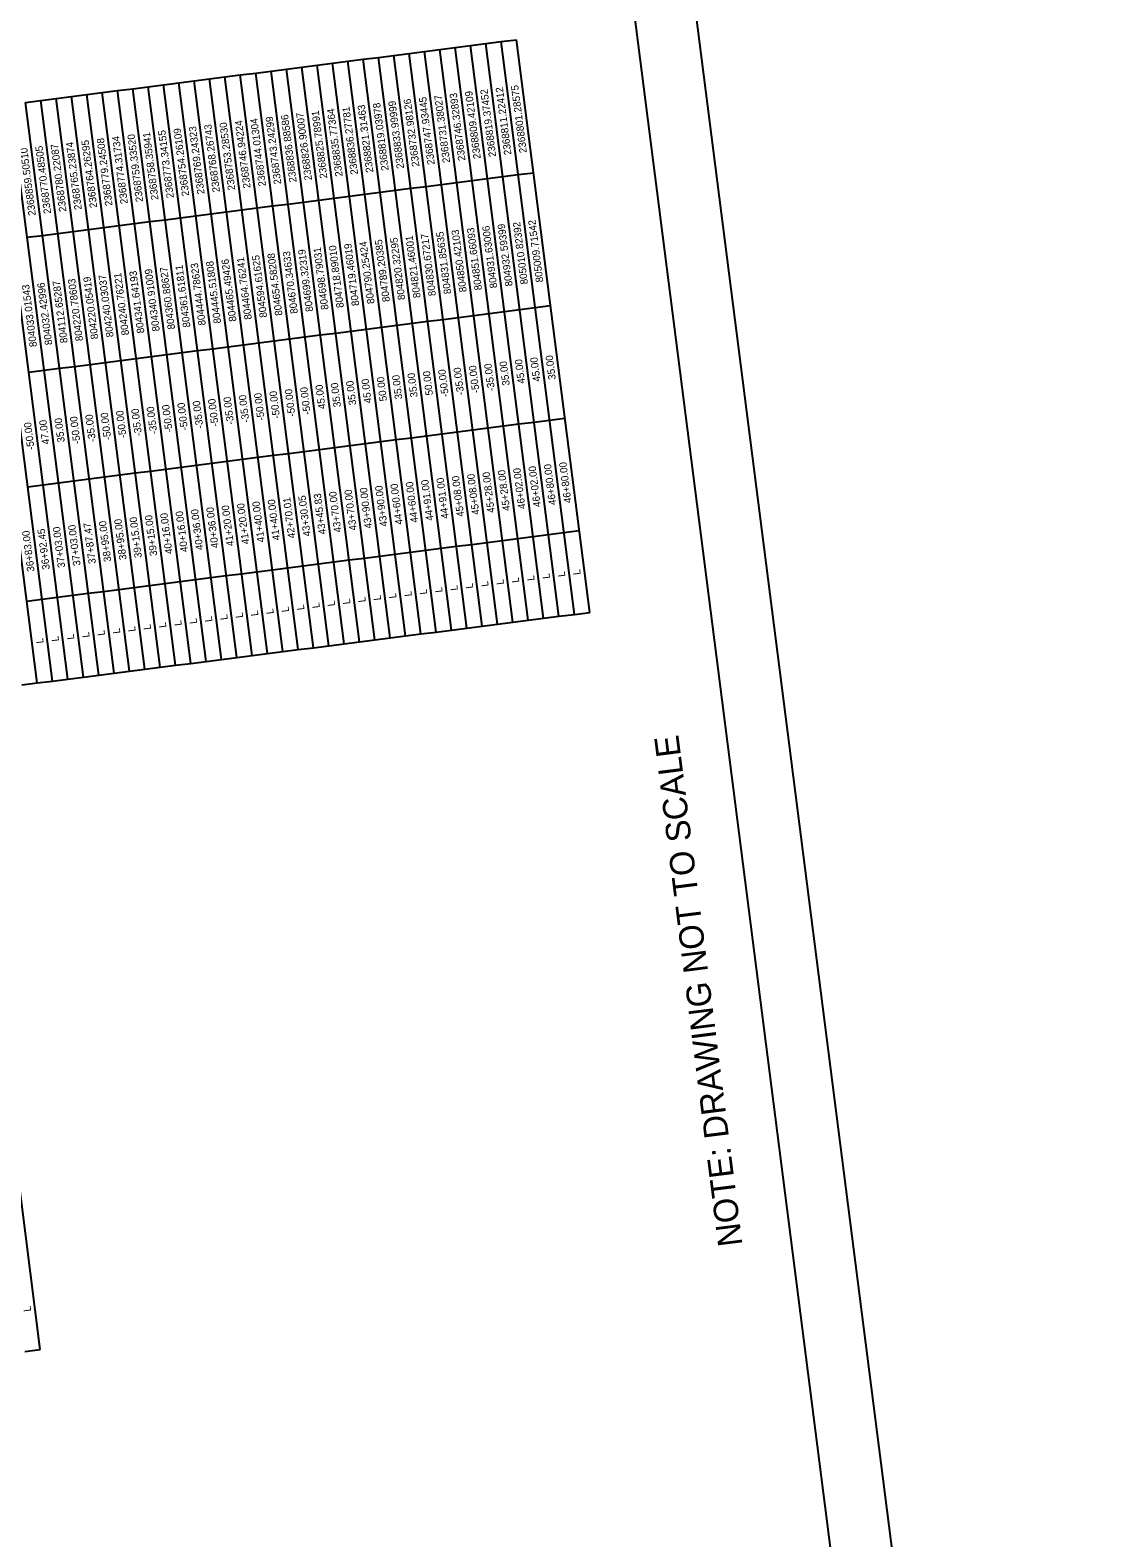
# Model space of a CAD drawing. Extents: x 2364621 to 2374814, y 792603 to 806745.
# Drawn here: x 2371409 to 2374814, y 798784 to 803612 of the extents above; entities that cross this region are included whole.
import ezdxf

# ---------------------------------------------------------------- set-up
doc = ezdxf.new("R2010")
doc.units = 0
for name, color, linetype in [('CTL Sheet Border CELL', 7, 'Continuous'), ('CTL Sheet Table Cell', 7, 'Continuous'), ('CTL Sheet Text', 7, 'Continuous'), ('Scratch_Level_0', 7, 'Continuous')]:
    doc.layers.add(name, color=color, linetype=linetype)

msp = doc.modelspace()

# ---------------------------------------------------------------- linework, layer by layer
at = {"layer": 'CTL Sheet Border CELL'}
msp.add_lwpolyline([(2364831.4, 805549.1), (2366316.3, 793922.1), (2374455.2, 794961.6), (2372970.2, 806588.6)], close=True, dxfattribs=at)
at = {"layer": 'CTL Sheet Table Cell'}
for p, q in [((2372917.1, 803575), (2372966.3, 803581.2)), ((2373200.5, 801747.5), (2372966.3, 803581.2)), ((2372524.2, 803524.8), (2372573.3, 803531)), ((2372573.3, 803531), (2372622.4, 803537.3)), ((2372807.5, 801697.3), (2372573.3, 803531)), ((2372622.4, 803537.3), (2372671.6, 803543.6)), ((2372856.6, 801703.6), (2372622.4, 803537.3)), ((2372671.6, 803543.6), (2372720.7, 803549.9)), ((2372905.8, 801709.9), (2372671.6, 803543.6)), ((2372720.7, 803549.9), (2372769.8, 803556.1)), ((2372954.9, 801716.1), (2372720.7, 803549.9)), ((2372769.8, 803556.1), (2372818.9, 803562.4)), ((2373004, 801722.4), (2372769.8, 803556.1)), ((2372818.9, 803562.4), (2372868, 803568.7)), ((2373053.1, 801728.7), (2372818.9, 803562.4)), ((2372868, 803568.7), (2372917.1, 803575)), ((2373102.2, 801735), (2372868, 803568.7)), ((2373151.4, 801741.2), (2372917.1, 803575)), ((2372180.4, 803480.9), (2372229.5, 803487.1)), ((2372229.5, 803487.1), (2372278.6, 803493.4)), ((2372463.7, 801653.4), (2372229.5, 803487.1)), ((2372278.6, 803493.4), (2372327.7, 803499.7)), ((2372512.8, 801659.7), (2372278.6, 803493.4)), ((2372327.7, 803499.7), (2372376.9, 803506)), ((2372561.9, 801665.9), (2372327.7, 803499.7)), ((2372376.9, 803506), (2372426, 803512.2)), ((2372611.1, 801672.2), (2372376.9, 803506)), ((2372426, 803512.2), (2372475.1, 803518.5)), ((2372660.2, 801678.5), (2372426, 803512.2)), ((2372475.1, 803518.5), (2372524.2, 803524.8)), ((2372709.3, 801684.8), (2372475.1, 803518.5)), ((2372758.4, 801691), (2372524.2, 803524.8)), ((2371787.4, 803430.7), (2371836.6, 803436.9)), ((2371836.6, 803436.9), (2371885.7, 803443.2)), ((2372070.8, 801603.2), (2371836.6, 803436.9)), ((2371885.7, 803443.2), (2371934.8, 803449.5)), ((2372119.9, 801609.5), (2371885.7, 803443.2)), ((2371934.8, 803449.5), (2371983.9, 803455.8)), ((2372169, 801615.8), (2371934.8, 803449.5)), ((2371983.9, 803455.8), (2372033, 803462)), ((2372218.1, 801622), (2371983.9, 803455.8)), ((2372033, 803462), (2372082.1, 803468.3)), ((2372267.2, 801628.3), (2372033, 803462)), ((2372082.1, 803468.3), (2372131.3, 803474.6)), ((2372316.3, 801634.6), (2372082.1, 803468.3)), ((2372131.3, 803474.6), (2372180.4, 803480.9)), ((2372365.5, 801640.9), (2372131.3, 803474.6)), ((2372414.6, 801647.1), (2372180.4, 803480.9)), ((2371394.5, 803380.5), (2371443.6, 803386.8)), ((2371443.6, 803386.8), (2371492.7, 803393)), ((2371677.8, 801553), (2371443.6, 803386.8)), ((2371492.7, 803393), (2371541.8, 803399.3)), ((2371726.9, 801559.3), (2371492.7, 803393)), ((2371541.8, 803399.3), (2371591, 803405.6)), ((2371776, 801565.6), (2371541.8, 803399.3)), ((2371591, 803405.6), (2371640.1, 803411.9)), ((2371825.2, 801571.8), (2371591, 803405.6)), ((2371640.1, 803411.9), (2371689.2, 803418.1)), ((2371874.3, 801578.1), (2371640.1, 803411.9)), ((2371689.2, 803418.1), (2371738.3, 803424.4)), ((2371923.4, 801584.4), (2371689.2, 803418.1)), ((2371738.3, 803424.4), (2371787.4, 803430.7)), ((2371972.5, 801590.7), (2371738.3, 803424.4)), ((2372021.6, 801596.9), (2371787.4, 803430.7)), ((2371432.2, 801521.7), (2371198, 803355.4)), ((2371481.3, 801527.9), (2371247.1, 803361.7)), ((2371530.5, 801534.2), (2371296.3, 803367.9)), ((2371579.6, 801540.5), (2371345.4, 803374.2)), ((2371628.7, 801546.8), (2371394.5, 803380.5)), ((2372922.4, 803143), (2372971.5, 803149.3)), ((2372971.5, 803149.3), (2373020.6, 803155.5)), ((2372529.5, 803092.8), (2372578.6, 803099.1)), ((2372578.6, 803099.1), (2372627.7, 803105.4)), ((2372627.7, 803105.4), (2372676.8, 803111.6)), ((2372676.8, 803111.6), (2372725.9, 803117.9)), ((2372725.9, 803117.9), (2372775, 803124.2)), ((2372775, 803124.2), (2372824.2, 803130.5)), ((2372824.2, 803130.5), (2372873.3, 803136.7)), ((2372873.3, 803136.7), (2372922.4, 803143)), ((2372136.5, 803042.6), (2372185.6, 803048.9)), ((2372185.6, 803048.9), (2372234.7, 803055.2)), ((2372234.7, 803055.2), (2372283.9, 803061.4)), ((2372283.9, 803061.4), (2372333, 803067.7)), ((2372333, 803067.7), (2372382.1, 803074)), ((2372382.1, 803074), (2372431.2, 803080.3)), ((2372431.2, 803080.3), (2372480.3, 803086.5)), ((2372480.3, 803086.5), (2372529.5, 803092.8)), ((2371743.6, 802992.4), (2371792.7, 802998.7)), ((2371792.7, 802998.7), (2371841.8, 803005)), ((2371841.8, 803005), (2371890.9, 803011.3)), ((2371890.9, 803011.3), (2371940, 803017.5)), ((2371940, 803017.5), (2371989.2, 803023.8)), ((2371989.2, 803023.8), (2372038.3, 803030.1)), ((2372038.3, 803030.1), (2372087.4, 803036.4)), ((2372087.4, 803036.4), (2372136.5, 803042.6)), ((2371399.7, 802948.5), (2371448.9, 802954.8)), ((2371448.9, 802954.8), (2371498, 802961.1)), ((2371498, 802961.1), (2371547.1, 802967.3)), ((2371547.1, 802967.3), (2371596.2, 802973.6)), ((2371596.2, 802973.6), (2371645.3, 802979.9)), ((2371645.3, 802979.9), (2371694.5, 802986.2)), ((2371694.5, 802986.2), (2371743.6, 802992.4)), ((2372878.5, 802704.8), (2372927.6, 802711)), ((2372927.6, 802711), (2372976.8, 802717.3)), ((2372976.8, 802717.3), (2373025.9, 802723.6)), ((2373025.9, 802723.6), (2373075, 802729.9)), ((2372485.6, 802654.6), (2372534.7, 802660.9)), ((2372534.7, 802660.9), (2372583.8, 802667.1)), ((2372583.8, 802667.1), (2372632.9, 802673.4)), ((2372632.9, 802673.4), (2372682.1, 802679.7)), ((2372682.1, 802679.7), (2372731.2, 802685.9)), ((2372731.2, 802685.9), (2372780.3, 802692.2)), ((2372780.3, 802692.2), (2372829.4, 802698.5)), ((2372829.4, 802698.5), (2372878.5, 802704.8)), ((2372141.8, 802610.7), (2372190.9, 802616.9)), ((2372190.9, 802616.9), (2372240, 802623.2)), ((2372240, 802623.2), (2372289.1, 802629.5)), ((2372289.1, 802629.5), (2372338.2, 802635.8)), ((2372338.2, 802635.8), (2372387.4, 802642)), ((2372387.4, 802642), (2372436.5, 802648.3)), ((2372436.5, 802648.3), (2372485.6, 802654.6)), ((2371748.8, 802560.5), (2371797.9, 802566.8)), ((2371797.9, 802566.8), (2371847.1, 802573)), ((2371847.1, 802573), (2371896.2, 802579.3)), ((2371896.2, 802579.3), (2371945.3, 802585.6)), ((2371945.3, 802585.6), (2371994.4, 802591.8)), ((2371994.4, 802591.8), (2372043.5, 802598.1)), ((2372043.5, 802598.1), (2372092.6, 802604.4)), ((2372092.6, 802604.4), (2372141.8, 802610.7)), ((2371405, 802516.6), (2371454.1, 802522.8)), ((2371454.1, 802522.8), (2371503.2, 802529.1)), ((2371503.2, 802529.1), (2371552.3, 802535.4)), ((2371552.3, 802535.4), (2371601.5, 802541.7)), ((2371601.5, 802541.7), (2371650.6, 802547.9)), ((2371650.6, 802547.9), (2371699.7, 802554.2)), ((2371699.7, 802554.2), (2371748.8, 802560.5)), ((2372728.1, 802319.5), (2372777.2, 802325.7)), ((2372777.2, 802325.7), (2372826.3, 802332)), ((2372826.3, 802332), (2372875.4, 802338.3)), ((2372875.4, 802338.3), (2372924.5, 802344.6)), ((2372924.5, 802344.6), (2372973.7, 802350.8)), ((2372973.7, 802350.8), (2373022.8, 802357.1)), ((2373022.8, 802357.1), (2373071.9, 802363.4)), ((2373071.9, 802363.4), (2373121, 802369.7)), ((2372335.1, 802269.3), (2372384.2, 802275.6)), ((2372384.2, 802275.6), (2372433.4, 802281.8)), ((2372433.4, 802281.8), (2372482.5, 802288.1)), ((2372482.5, 802288.1), (2372531.6, 802294.4)), ((2372531.6, 802294.4), (2372580.7, 802300.7)), ((2372580.7, 802300.7), (2372629.8, 802306.9)), ((2372629.8, 802306.9), (2372678.9, 802313.2)), ((2372678.9, 802313.2), (2372728.1, 802319.5)), ((2371991.3, 802225.4), (2372040.4, 802231.6)), ((2372040.4, 802231.6), (2372089.5, 802237.9)), ((2372089.5, 802237.9), (2372138.6, 802244.2)), ((2372138.6, 802244.2), (2372187.8, 802250.5)), ((2372187.8, 802250.5), (2372236.9, 802256.7)), ((2372236.9, 802256.7), (2372286, 802263)), ((2372286, 802263), (2372335.1, 802269.3)), ((2371598.4, 802175.2), (2371647.5, 802181.5)), ((2371647.5, 802181.5), (2371696.6, 802187.7)), ((2371696.6, 802187.7), (2371745.7, 802194)), ((2371745.7, 802194), (2371794.8, 802200.3)), ((2371794.8, 802200.3), (2371843.9, 802206.6)), ((2371843.9, 802206.6), (2371893.1, 802212.8)), ((2371893.1, 802212.8), (2371942.2, 802219.1)), ((2371942.2, 802219.1), (2371991.3, 802225.4)), ((2371401.9, 802150.1), (2371451, 802156.4)), ((2371451, 802156.4), (2371500.1, 802162.6)), ((2371500.1, 802162.6), (2371549.2, 802168.9)), ((2371549.2, 802168.9), (2371598.4, 802175.2)), ((2372970.5, 801984.4), (2373019.7, 801990.6)), ((2373019.7, 801990.6), (2373068.8, 801996.9)), ((2373068.8, 801996.9), (2373117.9, 802003.2)), ((2373117.9, 802003.2), (2373167, 802009.5)), ((2372577.6, 801934.2), (2372626.7, 801940.5)), ((2372626.7, 801940.5), (2372675.8, 801946.7)), ((2372675.8, 801946.7), (2372725, 801953)), ((2372725, 801953), (2372774.1, 801959.3)), ((2372774.1, 801959.3), (2372823.2, 801965.5)), ((2372823.2, 801965.5), (2372872.3, 801971.8)), ((2372872.3, 801971.8), (2372921.4, 801978.1)), ((2372921.4, 801978.1), (2372970.5, 801984.4)), ((2372184.7, 801884), (2372233.8, 801890.3)), ((2372233.8, 801890.3), (2372282.9, 801896.5)), ((2372282.9, 801896.5), (2372332, 801902.8)), ((2372332, 801902.8), (2372381.1, 801909.1)), ((2372381.1, 801909.1), (2372430.2, 801915.4)), ((2372430.2, 801915.4), (2372479.4, 801921.6)), ((2372479.4, 801921.6), (2372528.5, 801927.9)), ((2372528.5, 801927.9), (2372577.6, 801934.2)), ((2371791.7, 801833.8), (2371840.8, 801840.1)), ((2371840.8, 801840.1), (2371889.9, 801846.4)), ((2371889.9, 801846.4), (2371939.1, 801852.6)), ((2371939.1, 801852.6), (2371988.2, 801858.9)), ((2371988.2, 801858.9), (2372037.3, 801865.2)), ((2372037.3, 801865.2), (2372086.4, 801871.4)), ((2372086.4, 801871.4), (2372135.5, 801877.7)), ((2372135.5, 801877.7), (2372184.7, 801884)), ((2371447.9, 801789.9), (2371497, 801796.2)), ((2371497, 801796.2), (2371546.1, 801802.4)), ((2371546.1, 801802.4), (2371595.2, 801808.7)), ((2371595.2, 801808.7), (2371644.4, 801815)), ((2371644.4, 801815), (2371693.5, 801821.3)), ((2371693.5, 801821.3), (2371742.6, 801827.5)), ((2371742.6, 801827.5), (2371791.7, 801833.8)), ((2371398.8, 801783.6), (2371447.9, 801789.9)), ((2373151.4, 801741.2), (2373200.5, 801747.5)), ((2372758.4, 801691), (2372807.5, 801697.3)), ((2372807.5, 801697.3), (2372856.6, 801703.6)), ((2372856.6, 801703.6), (2372905.8, 801709.9)), ((2372905.8, 801709.9), (2372954.9, 801716.1)), ((2372954.9, 801716.1), (2373004, 801722.4)), ((2373004, 801722.4), (2373053.1, 801728.7)), ((2373053.1, 801728.7), (2373102.2, 801735)), ((2373102.2, 801735), (2373151.4, 801741.2)), ((2372365.5, 801640.9), (2372414.6, 801647.1)), ((2372414.6, 801647.1), (2372463.7, 801653.4)), ((2372463.7, 801653.4), (2372512.8, 801659.7)), ((2372512.8, 801659.7), (2372561.9, 801665.9)), ((2372561.9, 801665.9), (2372611.1, 801672.2)), ((2372611.1, 801672.2), (2372660.2, 801678.5)), ((2372660.2, 801678.5), (2372709.3, 801684.8)), ((2372709.3, 801684.8), (2372758.4, 801691)), ((2372021.6, 801596.9), (2372070.8, 801603.2)), ((2372070.8, 801603.2), (2372119.9, 801609.5)), ((2372119.9, 801609.5), (2372169, 801615.8)), ((2372169, 801615.8), (2372218.1, 801622)), ((2372218.1, 801622), (2372267.2, 801628.3)), ((2372267.2, 801628.3), (2372316.3, 801634.6)), ((2372316.3, 801634.6), (2372365.5, 801640.9)), ((2371628.7, 801546.8), (2371677.8, 801553)), ((2371677.8, 801553), (2371726.9, 801559.3)), ((2371726.9, 801559.3), (2371776, 801565.6)), ((2371776, 801565.6), (2371825.2, 801571.8)), ((2371825.2, 801571.8), (2371874.3, 801578.1)), ((2371874.3, 801578.1), (2371923.4, 801584.4)), ((2371923.4, 801584.4), (2371972.5, 801590.7)), ((2371972.5, 801590.7), (2372021.6, 801596.9)), ((2371383.1, 801515.4), (2371432.2, 801521.7)), ((2371432.2, 801521.7), (2371481.3, 801527.9)), ((2371481.3, 801527.9), (2371530.5, 801534.2)), ((2371530.5, 801534.2), (2371579.6, 801540.5)), ((2371579.6, 801540.5), (2371628.7, 801546.8)), ((2371441.6, 799387.5), (2371205.6, 801235.3)), ((2371392.1, 799381.2), (2371441.6, 799387.5))]:
    msp.add_line(p, q, dxfattribs=at)
at = {"layer": 'Scratch_Level_0'}
msp.add_lwpolyline([(2374814.3, 793692), (2373147.1, 806745.2), (2364620.8, 805656.2), (2366287.9, 792603)], close=True, dxfattribs=at)

# ---------------------------------------------------------------- texts
at = {"layer": 'CTL Sheet Border CELL'}
msp.add_text('NOTE: DRAWING NOT TO SCALE', height=78.143, rotation=97.1731, dxfattribs=at).set_placement((2373689.9, 799722.2))
at = {"layer": 'CTL Sheet Text'}
for s, height, p in [('2368801.28575', 23.579, (2372999.4, 803219.8)), ('2368833.99999', 23.579, (2372606.4, 803169.6)), ('2368732.98126', 23.579, (2372655.5, 803175.9)), ('2368747.93445', 23.579, (2372704.6, 803182.1)), ('2368731.38027', 23.579, (2372753.8, 803188.4)), ('2368746.32893', 23.579, (2372802.9, 803194.7)), ('2368809.42109', 23.579, (2372852, 803201)), ('2368819.37452', 23.579, (2372901.1, 803207.2)), ('2368811.22412', 23.579, (2372950.2, 803213.5)), ('2368836.88586', 23.579, (2372262.6, 803125.7)), ('2368826.90007', 23.579, (2372311.7, 803132)), ('2368825.78991', 23.579, (2372360.8, 803138.2)), ('2368835.77364', 23.579, (2372409.9, 803144.5)), ('2368836.27781', 23.579, (2372459.1, 803150.8)), ('2368821.31463', 23.579, (2372508.2, 803157)), ('2368819.03978', 23.579, (2372557.3, 803163.3)), ('2368773.34155', 23.579, (2371869.6, 803075.5)), ('2368754.26109', 23.579, (2371918.8, 803081.8)), ('2368769.24323', 23.579, (2371967.9, 803088)), ('2368768.26743', 23.579, (2372017, 803094.3)), ('2368753.28530', 23.579, (2372066.1, 803100.6)), ('2368746.94224', 23.579, (2372115.2, 803106.9)), ('2368744.01304', 23.579, (2372164.4, 803113.1)), ('2368743.24299', 23.579, (2372213.5, 803119.4)), ('2368770.48505', 23.579, (2371476.7, 803025.3)), ('2368780.22087', 23.579, (2371525.8, 803031.6)), ('2368765.23874', 23.579, (2371574.9, 803037.9)), ('2368764.26295', 23.579, (2371624.1, 803044.1)), ('2368779.24508', 23.579, (2371673.2, 803050.4)), ('2368774.31734', 23.579, (2371722.3, 803056.7)), ('2368759.33520', 23.579, (2371771.4, 803062.9)), ('2368758.35941', 23.579, (2371820.5, 803069.2)), ('2368859.50510', 23.579, (2371427.6, 803019)), ('805009.71542', 23.579, (2373052.2, 802805.7)), ('804821.46001', 23.579, (2372659.3, 802755.5)), ('804830.67217', 23.579, (2372708.4, 802761.8)), ('804831.85635', 23.579, (2372757.5, 802768.1)), ('804850.42103', 23.579, (2372806.7, 802774.3)), ('804851.66093', 23.579, (2372855.8, 802780.6)), ('804931.63006', 23.579, (2372904.9, 802786.9)), ('804932.59399', 23.579, (2372954, 802793.1)), ('805010.82392', 23.579, (2373003.1, 802799.4)), ('804670.34633', 23.579, (2372266.4, 802705.3)), ('804699.32319', 23.579, (2372315.5, 802711.6)), ('804698.79031', 23.579, (2372364.6, 802717.9)), ('804718.89010', 23.579, (2372413.7, 802724.1)), ('804719.46019', 23.579, (2372462.8, 802730.4)), ('804790.25424', 23.579, (2372511.9, 802736.7)), ('804789.20385', 23.579, (2372561.1, 802743)), ('804820.32295', 23.579, (2372610.2, 802749.2)), ('804361.61811', 23.579, (2371922.5, 802661.4)), ('804444.78623', 23.579, (2371971.6, 802667.7)), ('804445.51808', 23.579, (2372020.8, 802674)), ('804465.49426', 23.579, (2372069.9, 802680.2)), ('804464.76241', 23.579, (2372119, 802686.5)), ('804594.61625', 23.579, (2372168.1, 802692.8)), ('804654.58208', 23.579, (2372217.2, 802699)), ('804112.65287', 23.579, (2371529.6, 802611.2)), ('804220.78603', 23.579, (2371578.7, 802617.5)), ('804220.05419', 23.579, (2371627.8, 802623.8)), ('804240.03037', 23.579, (2371676.9, 802630)), ('804240.76221', 23.579, (2371726.1, 802636.3)), ('804341.64193', 23.579, (2371775.2, 802642.6)), ('804340.91009', 23.579, (2371824.3, 802648.9)), ('804360.88627', 23.579, (2371873.4, 802655.1)), ('804033.01543', 23.579, (2371431.4, 802598.7)), ('804032.42996', 23.579, (2371480.5, 802604.9)), ('45.00', 23.58, (2373042.9, 802487.7)), ('35.00', 23.58, (2373092.1, 802494)), ('50.00', 23.58, (2372699.1, 802443.8)), ('-50.00', 23.58, (2372749.7, 802438.5)), ('-35.00', 23.58, (2372798.8, 802444.7)), ('-50.00', 23.58, (2372847.9, 802451)), ('-35.00', 23.58, (2372897.1, 802457.3)), ('35.00', 23.58, (2372944.7, 802475.2)), ('45.00', 23.58, (2372993.8, 802481.4)), ('-50.00', 23.58, (2372307.7, 802382)), ('45.00', 23.58, (2372355.3, 802399.9)), ('35.00', 23.58, (2372404.4, 802406.1)), ('35.00', 23.58, (2372453.5, 802412.4)), ('45.00', 23.58, (2372502.6, 802418.7)), ('50.00', 23.58, (2372551.8, 802425)), ('35.00', 23.58, (2372600.9, 802431.2)), ('35.00', 23.58, (2372650, 802437.5)), ('-35.00', 23.58, (2371963.8, 802338.1)), ('-50.00', 23.58, (2372012.9, 802344.4)), ('-35.00', 23.58, (2372062.1, 802350.6)), ('-35.00', 23.58, (2372111.2, 802356.9)), ('-50.00', 23.58, (2372160.3, 802363.2)), ('-50.00', 23.58, (2372209.4, 802369.4)), ('-50.00', 23.58, (2372258.5, 802375.7)), ('-50.00', 23.58, (2371570.9, 802287.9)), ('-35.00', 23.58, (2371620, 802294.2)), ('-50.00', 23.58, (2371669.1, 802300.4)), ('-50.00', 23.58, (2371718.2, 802306.7)), ('-35.00', 23.58, (2371767.4, 802313)), ('-35.00', 23.58, (2371816.5, 802319.3)), ('-50.00', 23.58, (2371865.6, 802325.5)), ('-50.00', 23.58, (2371914.7, 802331.8)), ('-50.00', 23.58, (2371423.5, 802269.1)), ('47.00', 23.58, (2371471.2, 802287)), ('35.00', 23.58, (2371520.3, 802293.2)), ('46+80.00', 23.58, (2373142.5, 802099)), ('44+91.00', 23.58, (2372749.6, 802048.8)), ('45+08.00', 23.58, (2372798.7, 802055.1)), ('45+08.00', 23.58, (2372847.8, 802061.3)), ('45+28.00', 23.58, (2372896.9, 802067.6)), ('45+28.00', 23.58, (2372946, 802073.9)), ('46+02.00', 23.58, (2372995.2, 802080.1)), ('46+02.00', 23.58, (2373044.3, 802086.4)), ('46+80.00', 23.58, (2373093.4, 802092.7)), ('43+70.00', 23.58, (2372405.7, 802004.9)), ('43+70.00', 23.58, (2372454.9, 802011.1)), ('43+90.00', 23.58, (2372504, 802017.4)), ('43+90.00', 23.58, (2372553.1, 802023.7)), ('44+60.00', 23.58, (2372602.2, 802030)), ('44+60.00', 23.58, (2372651.3, 802036.2)), ('44+91.00', 23.58, (2372700.4, 802042.5)), ('40+36.00', 23.58, (2372012.8, 801954.7)), ('41+20.00', 23.58, (2372061.9, 801961)), ('41+20.00', 23.58, (2372111, 801967.2)), ('41+40.00', 23.58, (2372160.1, 801973.5)), ('41+40.00', 23.58, (2372209.3, 801979.8)), ('42+70.01', 23.58, (2372258.4, 801986)), ('43+30.05', 23.58, (2372307.5, 801992.3)), ('43+45.83', 23.58, (2372356.6, 801998.6)), ('38+95.00', 23.58, (2371669, 801910.8)), ('38+95.00', 23.58, (2371718.1, 801917)), ('39+15.00', 23.58, (2371767.2, 801923.3)), ('39+15.00', 23.58, (2371816.3, 801929.6)), ('40+16.00', 23.58, (2371865.4, 801935.9)), ('40+16.00', 23.58, (2371914.6, 801942.1)), ('40+36.00', 23.58, (2371963.7, 801948.4)), ('36+83.00', 23.58, (2371423.4, 801879.4)), ('36+92.45', 23.58, (2371472.5, 801885.7)), ('37+03.00', 23.58, (2371521.6, 801891.9)), ('37+03.00', 23.58, (2371570.7, 801898.2)), ('37+87.47', 23.58, (2371619.9, 801904.5)), ('L', 23.6, (2372828, 801825.2)), ('L', 23.6, (2372877.2, 801831.5)), ('L', 23.6, (2372926.3, 801837.7)), ('L', 23.6, (2372975.4, 801844)), ('L', 23.6, (2373024.5, 801850.3)), ('L', 23.6, (2373073.6, 801856.6)), ('L', 23.6, (2373122.7, 801862.8)), ('L', 23.6, (2373171.9, 801869.1)), ('L', 23.6, (2372484.2, 801781.3)), ('L', 23.6, (2372533.3, 801787.5)), ('L', 23.6, (2372582.4, 801793.8)), ('L', 23.6, (2372631.6, 801800.1)), ('L', 23.6, (2372680.7, 801806.4)), ('L', 23.6, (2372729.8, 801812.6)), ('L', 23.6, (2372778.9, 801818.9)), ('L', 23.6, (2372091.3, 801731.1)), ('L', 23.6, (2372140.4, 801737.4)), ('L', 23.6, (2372189.5, 801743.6)), ('L', 23.6, (2372238.6, 801749.9)), ('L', 23.6, (2372287.7, 801756.2)), ('L', 23.6, (2372336.9, 801762.5)), ('L', 23.6, (2372386, 801768.7)), ('L', 23.6, (2372435.1, 801775)), ('L', 23.6, (2371698.3, 801680.9)), ('L', 23.6, (2371747.4, 801687.2)), ('L', 23.6, (2371796.6, 801693.5)), ('L', 23.6, (2371845.7, 801699.7)), ('L', 23.6, (2371894.8, 801706)), ('L', 23.6, (2371943.9, 801712.3)), ('L', 23.6, (2371993, 801718.5)), ('L', 23.6, (2372042.2, 801724.8)), ('L', 23.6, (2371452.7, 801649.5)), ('L', 23.6, (2371501.9, 801655.8)), ('L', 23.6, (2371551, 801662.1)), ('L', 23.6, (2371600.1, 801668.4)), ('L', 23.6, (2371649.2, 801674.6)), ('L', 23.8, (2371412.8, 799510.1))]:
    msp.add_text(s, height=height, rotation=97.2784, dxfattribs=at).set_placement(p)

doc.saveas('drawing.dxf')
